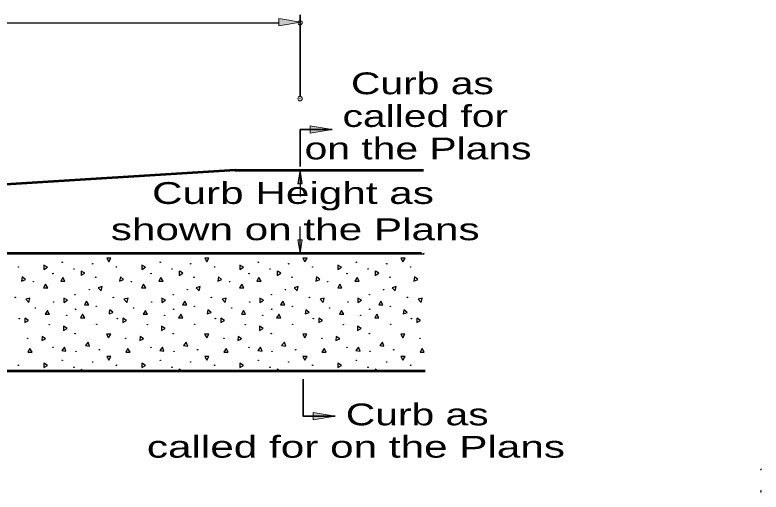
# Model space of a CAD drawing. Extents: x 75.6 to 110.9, y 28 to 50.
# Drawn here: x 87.79 to 92.93, y 36.1 to 39.38 of the extents above; entities that cross this region are included whole.
import ezdxf

# ---------------------------------------------------------------- set-up
doc = ezdxf.new("R2010")
doc.units = 0
doc.header["$LTSCALE"] = 0.06
doc.header["$PDMODE"] = 32
doc.header["$PDSIZE"] = 0.03
doc.layers.add('1', color=7, linetype='Continuous', lineweight=25)
doc.layers.add('3', color=7, linetype='Continuous', lineweight=13)

msp = doc.modelspace()

# ---------------------------------------------------------------- hatches: boundary and pattern name
at = {"layer": '3'}
for points in [[(89.60942, 39.3575), (89.60942, 39.3075), (89.75942, 39.3325), (89.75942, 39.3325)], [(89.82533, 38.61892), (89.82533, 38.56892), (89.97533, 38.59392), (89.97533, 38.59392)], [(89.74017, 38.22367), (89.77092, 38.22367), (89.75558, 38.31592), (89.75558, 38.31592)], [(89.74017, 37.83583), (89.77092, 37.83583), (89.75558, 37.74358), (89.75558, 37.74358)], [(89.84592, 36.59792), (89.84592, 36.64792), (89.99592, 36.62292), (89.99592, 36.62292)]]:
    msp.add_hatch(color=256, dxfattribs=at).paths.add_polyline_path(points)

# ---------------------------------------------------------------- linework, layer by layer
at = {"layer": '1', "lineweight": 53}
for p, q in [((89.3085, 38.31592), (83.31608, 37.94033)), ((89.3085, 38.31592), (90.60442, 38.31592)), ((83.26617, 37.74358), (90.5905, 37.74358)), ((90.61742, 36.932), (83.26817, 36.932))]:
    msp.add_line(p, q, dxfattribs=at)
at = {"layer": '1'}
for p, q in [((87.88375, 37.74358), (87.88117, 37.73917)), ((88.55875, 37.74358), (88.55617, 37.73917)), ((89.23375, 37.74358), (89.23117, 37.73917)), ((89.90875, 37.74358), (89.90617, 37.73917)), ((90.58375, 37.74358), (90.58117, 37.73917)), ((88.24825, 37.6205), (88.24817, 37.59142)), ((88.25408, 37.61717), (88.24825, 37.6205)), ((88.25408, 37.61717), (88.24825, 37.6205)), ((88.92325, 37.6205), (88.92317, 37.59142)), ((88.92908, 37.61717), (88.92325, 37.6205)), ((88.92908, 37.61717), (88.92325, 37.6205)), ((89.59825, 37.6205), (89.59817, 37.59142)), ((89.60408, 37.61717), (89.59825, 37.6205)), ((89.60408, 37.61717), (89.59825, 37.6205)), ((90.27325, 37.6205), (90.27317, 37.59142)), ((90.27908, 37.61717), (90.27325, 37.6205)), ((90.27908, 37.61717), (90.27325, 37.6205)), ((88.24817, 37.59142), (88.25408, 37.59475)), ((88.92317, 37.59142), (88.92908, 37.59475)), ((89.59817, 37.59142), (89.60408, 37.59475)), ((90.27317, 37.59142), (90.27908, 37.59475)), ((88.00975, 37.338), (88.00125, 37.32358)), ((88.00125, 37.32358), (88.0305, 37.32358)), ((88.0305, 37.32358), (88.02208, 37.338)), ((88.25408, 37.316), (88.24417, 37.29892)), ((88.24417, 37.29892), (88.25408, 37.29892)), ((88.25875, 37.32408), (88.25408, 37.316)), ((88.25408, 37.29892), (88.27325, 37.29892)), ((88.27325, 37.29892), (88.25875, 37.32408)), ((88.44225, 37.338), (88.44025, 37.32658)), ((88.44025, 37.32658), (88.4675, 37.33667)), ((88.4675, 37.33667), (88.46583, 37.338)), ((88.68475, 37.338), (88.67625, 37.32358)), ((88.67625, 37.32358), (88.7055, 37.32358)), ((88.7055, 37.32358), (88.69708, 37.338)), ((88.92908, 37.316), (88.91917, 37.29892)), ((88.91917, 37.29892), (88.92908, 37.29892)), ((88.93375, 37.32408), (88.92908, 37.316)), ((88.92908, 37.29892), (88.94825, 37.29892)), ((88.94825, 37.29892), (88.93375, 37.32408)), ((89.11725, 37.338), (89.11525, 37.32658)), ((89.11525, 37.32658), (89.1425, 37.33667)), ((89.1425, 37.33667), (89.14083, 37.338)), ((89.35975, 37.338), (89.35125, 37.32358)), ((89.35125, 37.32358), (89.3805, 37.32358)), ((89.3805, 37.32358), (89.37208, 37.338)), ((89.60408, 37.316), (89.59417, 37.29892)), ((89.59417, 37.29892), (89.60408, 37.29892)), ((89.60875, 37.32408), (89.60408, 37.316)), ((89.60408, 37.29892), (89.62325, 37.29892)), ((89.62325, 37.29892), (89.60875, 37.32408)), ((89.79225, 37.338), (89.79025, 37.32658)), ((89.79025, 37.32658), (89.8175, 37.33667)), ((89.8175, 37.33667), (89.81583, 37.338)), ((90.03475, 37.338), (90.02625, 37.32358)), ((90.02625, 37.32358), (90.0555, 37.32358)), ((90.0555, 37.32358), (90.04708, 37.338)), ((90.27908, 37.316), (90.26917, 37.29892)), ((90.26917, 37.29892), (90.27908, 37.29892)), ((90.28375, 37.32408), (90.27908, 37.316)), ((90.27908, 37.29892), (90.29825, 37.29892)), ((90.29825, 37.29892), (90.28375, 37.32408)), ((90.46725, 37.338), (90.46525, 37.32658)), ((90.46525, 37.32658), (90.4925, 37.33667)), ((90.4925, 37.33667), (90.49083, 37.338)), ((88.24825, 36.9455), (88.24825, 36.932)), ((88.24825, 36.9455), (88.24825, 36.932)), ((88.25408, 36.94217), (88.24825, 36.9455)), ((88.25408, 36.94217), (88.24825, 36.9455)), ((88.27158, 36.932), (88.25408, 36.94217)), ((88.92325, 36.9455), (88.92325, 36.932)), ((88.92325, 36.9455), (88.92325, 36.932)), ((88.92908, 36.94217), (88.92325, 36.9455)), ((88.92908, 36.94217), (88.92325, 36.9455)), ((88.94658, 36.932), (88.92908, 36.94217)), ((89.59825, 36.9455), (89.59825, 36.932)), ((89.59825, 36.9455), (89.59825, 36.932)), ((89.60408, 36.94217), (89.59825, 36.9455)), ((89.60408, 36.94217), (89.59825, 36.9455)), ((89.62158, 36.932), (89.60408, 36.94217)), ((90.27325, 36.9455), (90.27325, 36.932)), ((90.27325, 36.9455), (90.27325, 36.932)), ((90.27908, 36.94217), (90.27325, 36.9455)), ((90.27908, 36.94217), (90.27325, 36.9455)), ((90.29658, 36.932), (90.27908, 36.94217)), ((92.92467, 36.26075), (92.92858, 36.25392)), ((92.92858, 36.25392), (92.92467, 36.25392)), ((92.92467, 36.11117), (92.927, 36.1125)), ((92.92467, 36.11117), (92.927, 36.1125)), ((92.927, 36.1125), (92.927, 36.10083)), ((92.927, 36.1125), (92.927, 36.10083)), ((92.927, 36.10083), (92.92467, 36.10225)), ((92.927, 36.10083), (92.92467, 36.10225))]:
    msp.add_line(p, q, dxfattribs=at)
for points in [[(87.88117, 37.73917), (87.91025, 37.73917), (87.90767, 37.74358)], [(88.55617, 37.73917), (88.58525, 37.73917), (88.58267, 37.74358)], [(89.23117, 37.73917), (89.26025, 37.73917), (89.25767, 37.74358)], [(89.90617, 37.73917), (89.93525, 37.73917), (89.93267, 37.74358)], [(90.58117, 37.73917), (90.61025, 37.73917), (90.60767, 37.74358)], [(88.24825, 37.6205), (88.24817, 37.59142), (88.25408, 37.59475)], [(88.25408, 37.59475), (88.27342, 37.60592), (88.25408, 37.61717)], [(88.92325, 37.6205), (88.92317, 37.59142), (88.92908, 37.59475)], [(88.92908, 37.59475), (88.94842, 37.60592), (88.92908, 37.61717)], [(89.59825, 37.6205), (89.59817, 37.59142), (89.60408, 37.59475)], [(89.60408, 37.59475), (89.62342, 37.60592), (89.60408, 37.61717)], [(90.27325, 37.6205), (90.27317, 37.59142), (90.27908, 37.59475)], [(90.27908, 37.59475), (90.29842, 37.60592), (90.27908, 37.61717)], [(88.02208, 37.338), (88.01592, 37.34867), (88.00975, 37.338)], [(88.46583, 37.338), (88.44533, 37.35517), (88.44225, 37.338)], [(88.46583, 37.338), (88.44533, 37.35517), (88.44225, 37.338)], [(88.69708, 37.338), (88.69092, 37.34867), (88.68475, 37.338)], [(89.14083, 37.338), (89.12033, 37.35517), (89.11725, 37.338)], [(89.14083, 37.338), (89.12033, 37.35517), (89.11725, 37.338)], [(89.37208, 37.338), (89.36592, 37.34867), (89.35975, 37.338)], [(89.81583, 37.338), (89.79533, 37.35517), (89.79225, 37.338)], [(89.81583, 37.338), (89.79533, 37.35517), (89.79225, 37.338)], [(90.04708, 37.338), (90.04092, 37.34867), (90.03475, 37.338)], [(90.49083, 37.338), (90.47033, 37.35517), (90.46725, 37.338)], [(90.49083, 37.338), (90.47033, 37.35517), (90.46725, 37.338)]]:
    msp.add_lwpolyline(points, dxfattribs=at)
for points in [[(88.43883, 37.68408), (88.4535, 37.70933), (88.42433, 37.70933)], [(89.11383, 37.68408), (89.1285, 37.70933), (89.09933, 37.70933)], [(89.78883, 37.68408), (89.8035, 37.70933), (89.77433, 37.70933)], [(90.46383, 37.68408), (90.4785, 37.70933), (90.44933, 37.70933)], [(87.99108, 37.63275), (88.01633, 37.64733), (87.99125, 37.66192)], [(88.66608, 37.63275), (88.69133, 37.64733), (88.66625, 37.66192)], [(89.34108, 37.63275), (89.36633, 37.64733), (89.34125, 37.66192)], [(90.01608, 37.63275), (90.04133, 37.64733), (90.01625, 37.66192)], [(87.83825, 37.55192), (87.86558, 37.56192), (87.84333, 37.5805)], [(88.108, 37.55258), (88.13708, 37.55258), (88.12258, 37.57767)], [(88.51325, 37.55192), (88.54058, 37.56192), (88.51833, 37.5805)], [(88.783, 37.55258), (88.81208, 37.55258), (88.79758, 37.57767)], [(89.18825, 37.55192), (89.21558, 37.56192), (89.19333, 37.5805)], [(89.458, 37.55258), (89.48708, 37.55258), (89.47258, 37.57767)], [(89.86325, 37.55192), (89.89058, 37.56192), (89.86833, 37.5805)], [(90.133, 37.55258), (90.16208, 37.55258), (90.14758, 37.57767)], [(90.53825, 37.55192), (90.56558, 37.56192), (90.54333, 37.5805)], [(87.98917, 37.50533), (88.01825, 37.50533), (88.00375, 37.5305)], [(88.38525, 37.48592), (88.39275, 37.51417), (88.36475, 37.50658)], [(88.66417, 37.50533), (88.69325, 37.50533), (88.67875, 37.5305)], [(89.06025, 37.48592), (89.06775, 37.51417), (89.03975, 37.50658)], [(89.33917, 37.50533), (89.36825, 37.50533), (89.35375, 37.5305)], [(89.73525, 37.48592), (89.74275, 37.51417), (89.71475, 37.50658)], [(90.01417, 37.50533), (90.04325, 37.50533), (90.02875, 37.5305)], [(90.41025, 37.48592), (90.41775, 37.51417), (90.38975, 37.50658)], [(87.88867, 37.40592), (87.89617, 37.43408), (87.86808, 37.42658)], [(88.12867, 37.40592), (88.15392, 37.4205), (88.12883, 37.43508)], [(88.27175, 37.38892), (88.30092, 37.38892), (88.28642, 37.41417)], [(88.56367, 37.40592), (88.57117, 37.43408), (88.54308, 37.42658)], [(88.80367, 37.40592), (88.82892, 37.4205), (88.80383, 37.43508)], [(88.94675, 37.38892), (88.97592, 37.38892), (88.96142, 37.41417)], [(89.23867, 37.40592), (89.24617, 37.43408), (89.21808, 37.42658)], [(89.47867, 37.40592), (89.50392, 37.4205), (89.47883, 37.43508)], [(89.62175, 37.38892), (89.65092, 37.38892), (89.63642, 37.41417)], [(89.91367, 37.40592), (89.92117, 37.43408), (89.89308, 37.42658)], [(90.15367, 37.40592), (90.17892, 37.4205), (90.15383, 37.43508)], [(90.29675, 37.38892), (90.32592, 37.38892), (90.31142, 37.41417)], [(90.58867, 37.40592), (90.59617, 37.43408), (90.56808, 37.42658)], [(87.86, 37.2675), (87.88525, 37.28208), (87.86017, 37.29667)], [(88.535, 37.2675), (88.56025, 37.28208), (88.53517, 37.29667)], [(89.21, 37.2675), (89.23525, 37.28208), (89.21017, 37.29667)], [(89.885, 37.2675), (89.91025, 37.28208), (89.88517, 37.29667)], [(90.56, 37.2675), (90.58525, 37.28208), (90.56017, 37.29667)], [(88.126, 37.21175), (88.15125, 37.22642), (88.12617, 37.24092)], [(88.801, 37.21175), (88.82625, 37.22642), (88.80117, 37.24092)], [(89.476, 37.21175), (89.50125, 37.22642), (89.47617, 37.24092)], [(90.151, 37.21175), (90.17625, 37.22642), (90.15117, 37.24092)], [(88.43775, 37.16117), (88.45233, 37.18642), (88.42325, 37.18642)], [(89.11275, 37.16117), (89.12733, 37.18642), (89.09825, 37.18642)], [(89.78775, 37.16117), (89.80233, 37.18642), (89.77325, 37.18642)], [(90.46275, 37.16117), (90.47733, 37.18642), (90.44825, 37.18642)], [(87.97692, 37.14233), (88.00333, 37.15458), (87.9795, 37.17125)], [(88.65192, 37.14233), (88.67833, 37.15458), (88.6545, 37.17125)], [(89.32692, 37.14233), (89.35333, 37.15458), (89.3295, 37.17125)], [(90.00192, 37.14233), (90.02833, 37.15458), (90.0045, 37.17125)], [(87.88117, 37.06417), (87.91025, 37.06417), (87.89575, 37.08925)], [(88.11483, 37.07575), (88.1435, 37.07067), (88.1335, 37.09808)], [(88.27833, 37.10925), (88.307, 37.10417), (88.29708, 37.1315)], [(88.55617, 37.06417), (88.58525, 37.06417), (88.57075, 37.08925)], [(88.78983, 37.07575), (88.8185, 37.07067), (88.8085, 37.09808)], [(88.95333, 37.10925), (88.982, 37.10417), (88.97208, 37.1315)], [(89.23117, 37.06417), (89.26025, 37.06417), (89.24575, 37.08925)], [(89.46483, 37.07575), (89.4935, 37.07067), (89.4835, 37.09808)], [(89.62833, 37.10925), (89.657, 37.10417), (89.64708, 37.1315)], [(89.90617, 37.06417), (89.93525, 37.06417), (89.92075, 37.08925)], [(90.13983, 37.07575), (90.1685, 37.07067), (90.1585, 37.09808)], [(90.30333, 37.10925), (90.332, 37.10417), (90.32208, 37.1315)], [(90.58117, 37.06417), (90.61025, 37.06417), (90.59575, 37.08925)], [(88.43883, 37.00908), (88.4535, 37.03433), (88.42433, 37.03433)], [(89.11383, 37.00908), (89.1285, 37.03433), (89.09933, 37.03433)], [(89.78883, 37.00908), (89.8035, 37.03433), (89.77433, 37.03433)], [(90.46383, 37.00908), (90.4785, 37.03433), (90.44933, 37.03433)], [(87.99108, 36.95775), (88.01633, 36.97233), (87.99125, 36.98692)], [(88.66608, 36.95775), (88.69133, 36.97233), (88.66625, 36.98692)], [(89.34108, 36.95775), (89.36633, 36.97233), (89.34125, 36.98692)], [(90.01608, 36.95775), (90.04133, 36.97233), (90.01625, 36.98692)]]:
    msp.add_lwpolyline(points, close=True, dxfattribs=at)
for centre in [(87.81674, 37.64856), (88.11796, 37.68203), (88.32721, 37.67089), (88.49174, 37.64856), (88.79296, 37.68203), (89.00221, 37.67089), (89.16674, 37.64856), (89.46796, 37.68203), (89.67721, 37.67089), (89.84174, 37.64856), (90.14296, 37.68203), (90.35221, 37.67089), (90.51674, 37.64856), (88.05383, 37.60395), (88.19885, 37.63461), (88.72883, 37.60395), (88.87385, 37.63461), (89.40383, 37.60395), (89.54885, 37.63461), (90.07883, 37.60395), (90.22385, 37.63461), (87.91996, 37.54815), (88.34948, 37.57886), (88.59496, 37.54815), (89.02448, 37.57886), (89.26996, 37.54815), (89.69948, 37.57886), (89.94496, 37.54815), (90.37448, 37.57886), (88.30488, 37.49241), (88.97988, 37.49241), (89.65488, 37.49241), (90.32988, 37.49241), (87.79441, 37.43936), (88.20723, 37.45894), (88.46941, 37.43936), (88.88223, 37.45894), (89.14441, 37.43936), (89.55723, 37.45894), (89.81941, 37.43936), (90.23223, 37.45894), (90.49441, 37.43936), (88.0594, 37.40871), (88.7344, 37.40871), (89.4094, 37.40871), (90.0844, 37.40871), (87.93391, 37.36686), (88.20998, 37.35853), (88.3523, 37.37805), (88.60891, 37.36686), (88.88498, 37.35853), (89.0273, 37.37805), (89.28391, 37.36686), (89.55998, 37.35853), (89.7023, 37.37805), (89.95891, 37.36686), (90.23498, 37.35853), (90.3773, 37.37805), (87.82231, 37.29429), (88.14861, 37.31663), (88.49731, 37.29429), (88.82361, 37.31663), (89.17231, 37.29429), (89.49861, 37.31663), (89.84731, 37.29429), (90.17361, 37.31663), (90.52231, 37.29429), (88.02869, 37.2525), (88.35505, 37.25526), (88.70369, 37.2525), (89.03005, 37.25526), (89.37869, 37.2525), (89.70505, 37.25526), (90.05369, 37.2525), (90.38005, 37.25526), (88.20723, 37.19113), (88.88223, 37.19113), (89.55723, 37.19113), (90.23223, 37.19113), (87.88086, 37.15766), (88.55586, 37.15766), (89.23086, 37.15766), (89.90586, 37.15766), (90.58086, 37.15766), (88.05383, 37.09629), (88.72883, 37.09629), (89.40383, 37.09629), (90.07883, 37.09629), (88.2128, 37.06839), (88.37463, 37.07953), (88.8878, 37.06839), (89.04963, 37.07953), (89.5628, 37.06839), (89.72463, 37.07953), (90.2378, 37.06839), (90.39963, 37.07953), (88.11796, 37.00703), (88.32721, 36.99589), (88.79296, 37.00703), (89.00221, 36.99589), (89.46796, 37.00703), (89.67721, 36.99589), (90.14296, 37.00703), (90.35221, 36.99589), (87.81674, 36.97356), (88.19885, 36.95961), (88.49174, 36.97356), (88.87385, 36.95961), (89.16674, 36.97356), (89.54885, 36.95961), (89.84174, 36.97356), (90.22385, 36.95961), (90.51674, 36.97356)]:
    msp.add_circle(centre, 0.00162, dxfattribs=at)
for centre in [(88.2128, 37.74339), (88.8878, 37.74339), (89.5628, 37.74339), (90.2378, 37.74339)]:
    msp.add_arc(centre, 0.00162, 173.26839, 6.73161, dxfattribs=at)
at = {"layer": '3', "lineweight": 35}
for p, q in [((89.75558, 38.82558), (89.75558, 39.38283)), ((89.75558, 38.33983), (89.75558, 38.59392)), ((89.75558, 38.59392), (89.97533, 38.59392))]:
    msp.add_line(p, q, dxfattribs=at)
at = {"layer": '3', "lineweight": 25}
for p, q in [((83.42208, 39.32883), (89.60558, 39.32883)), ((89.75558, 38.31592), (89.75558, 38.133)), ((89.75558, 37.74358), (89.75558, 37.92642))]:
    msp.add_line(p, q, dxfattribs=at)
at = {"layer": '3'}
for points in [[(89.60942, 39.3575), (89.60942, 39.3075), (89.75942, 39.3325), (89.75942, 39.3325)], [(89.82533, 38.61892), (89.82533, 38.56892), (89.97533, 38.59392), (89.97533, 38.59392)], [(89.74017, 37.83583), (89.77092, 37.83583), (89.75558, 37.74358), (89.75558, 37.74358)], [(89.84592, 36.59792), (89.84592, 36.64792), (89.99592, 36.62292), (89.99592, 36.62292)]]:
    msp.add_lwpolyline(points, close=True, dxfattribs=at)
at = {"layer": '3', "lineweight": 25}
msp.add_lwpolyline([(89.74017, 38.22367), (89.77092, 38.22367), (89.75558, 38.31592), (89.75558, 38.31592)], close=True, dxfattribs=at)
at = {"layer": '3', "lineweight": 35}
msp.add_lwpolyline([(89.77617, 36.877), (89.77617, 36.62292), (89.99592, 36.62292)], dxfattribs=at)
at = {"layer": '3'}
for p in [(89.75558, 39.32883), (89.75558, 38.80683)]:
    msp.add_point(p, dxfattribs=at)

# ---------------------------------------------------------------- texts
for s, width, p in [('Curb as', 1.4, (90.10575, 38.83733)), ('called for', 1.4, (90.048, 38.61242)), (' on the Plans', 1.4, (89.70883, 38.3895)), ('Curb Height as ', 1.45, (88.73658, 38.08283)), ('shown on the Plans', 1.45, (88.45267, 37.83325)), ('Curb as', 1.4, (90.07008, 36.55983)), ('called for on the Plans', 1.45, (88.70108, 36.33733))]:
    msp.add_text(s, height=0.15, dxfattribs=dict(at, width=width)).set_placement(p)

doc.saveas('drawing.dxf')
